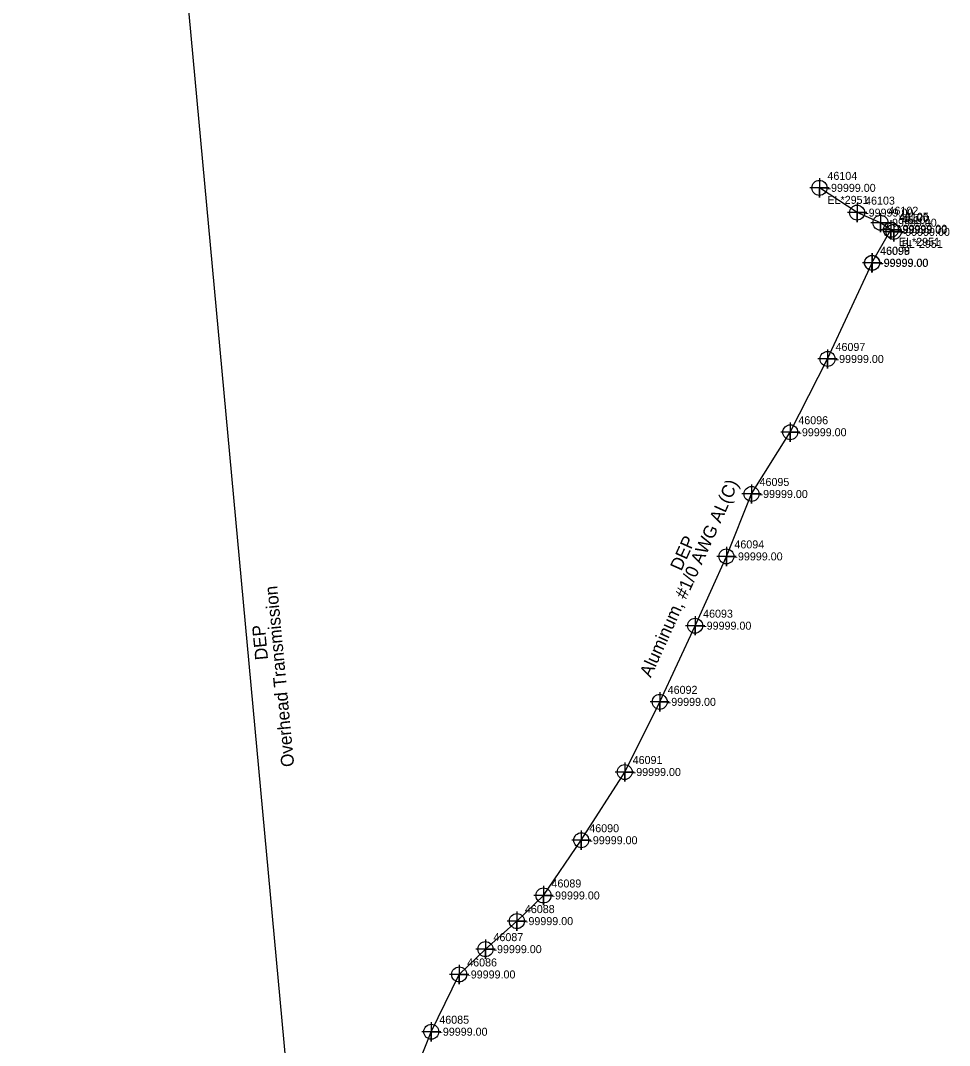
# Model space of a CAD drawing. Extents: x 2083698 to 2094313, y 743246 to 752873.
# Drawn here: x 2090968.3 to 2091258.4, y 750579.9 to 750900 of the extents above; entities that cross this region are included whole.
import ezdxf

# ---------------------------------------------------------------- set-up
doc = ezdxf.new("R2010")
doc.units = 0
for name, color, linetype in [('Exist Property Iron Pin Leader', 7, 'Continuous'), ('Exist Property Iron Pin Text', 7, 'Continuous'), ('Exist Property Monument Leader', 7, 'Continuous'), ('Exist Property Monument Text', 7, 'Continuous'), ('Exist Utilities Power Joint Use Telephone Cogo Elevation', 7, 'Continuous'), ('Exist Utilities Power Joint Use Telephone Cogo Number', 7, 'Continuous'), ('Exist Utilities Power UG Cable SUE LOS B', 7, 'Continuous'), ('Exist Utilities Power UG Cable SUE LOS B Text', 7, 'Continuous'), ('Exist Utilities Power UG Cable SUE LOS C', 7, 'Continuous'), ('Exist Utilities Power UG Cable SUE LOS C Text', 7, 'Continuous')]:
    doc.layers.add(name, color=color, linetype=linetype)

msp = doc.modelspace()

# ---------------------------------------------------------------- linework, layer by layer
at = {"layer": 'Exist Property Iron Pin Text'}
for points in [[(2091217.8, 750850.78), (2091217.8, 750844.78), (2091217.8, 750847.78), (2091220.8, 750847.78), (2091214.8, 750847.78)], [(2091229.56, 750843.04), (2091229.56, 750837.04), (2091229.56, 750840.04), (2091232.56, 750840.04), (2091226.56, 750840.04)], [(2091236.86, 750839.89), (2091236.86, 750833.89), (2091236.86, 750836.89), (2091239.86, 750836.89), (2091233.86, 750836.89)], [(2091240.12, 750837.67), (2091240.12, 750831.67), (2091240.12, 750834.67), (2091243.12, 750834.67), (2091237.12, 750834.67)], [(2091240.98, 750837.03), (2091240.98, 750831.03), (2091240.98, 750834.03), (2091243.98, 750834.03), (2091237.98, 750834.03)], [(2091234.21, 750827.33), (2091234.21, 750821.33), (2091234.21, 750824.33), (2091237.21, 750824.33), (2091231.21, 750824.33)], [(2091234.28, 750827.4), (2091234.28, 750821.4), (2091234.28, 750824.4), (2091237.28, 750824.4), (2091231.28, 750824.4)], [(2091220.33, 750797.34), (2091220.33, 750791.34), (2091220.33, 750794.34), (2091223.33, 750794.34), (2091217.33, 750794.34)], [(2091208.71, 750774.45), (2091208.71, 750768.45), (2091208.71, 750771.45), (2091211.71, 750771.45), (2091205.71, 750771.45)], [(2091196.6, 750755.17), (2091196.6, 750749.17), (2091196.6, 750752.17), (2091199.6, 750752.17), (2091193.6, 750752.17)], [(2091188.75, 750735.67), (2091188.75, 750729.67), (2091188.75, 750732.67), (2091191.75, 750732.67), (2091185.75, 750732.67)], [(2091178.98, 750714.03), (2091178.98, 750708.03), (2091178.98, 750711.03), (2091181.98, 750711.03), (2091175.98, 750711.03)], [(2091167.92, 750690.24), (2091167.92, 750684.24), (2091167.92, 750687.24), (2091170.92, 750687.24), (2091164.92, 750687.24)], [(2091156.99, 750668.33), (2091156.99, 750662.33), (2091156.99, 750665.33), (2091159.99, 750665.33), (2091153.99, 750665.33)], [(2091143.44, 750647.02), (2091143.44, 750641.02), (2091143.44, 750644.02), (2091146.44, 750644.02), (2091140.44, 750644.02)], [(2091131.64, 750629.77), (2091131.64, 750623.77), (2091131.64, 750626.77), (2091134.64, 750626.77), (2091128.64, 750626.77)], [(2091123.33, 750621.76), (2091123.33, 750615.76), (2091123.33, 750618.76), (2091126.33, 750618.76), (2091120.33, 750618.76)], [(2091113.52, 750613), (2091113.52, 750607), (2091113.52, 750610), (2091116.52, 750610), (2091110.52, 750610)], [(2091105.32, 750605.1), (2091105.32, 750599.1), (2091105.32, 750602.1), (2091108.32, 750602.1), (2091102.32, 750602.1)], [(2091096.61, 750587.21), (2091096.61, 750581.21), (2091096.61, 750584.21), (2091099.61, 750584.21), (2091093.61, 750584.21)]]:
    msp.add_lwpolyline(points, dxfattribs=at)
for centre in [(2091217.8, 750847.78), (2091229.56, 750840.04), (2091236.86, 750836.89), (2091240.12, 750834.67), (2091240.98, 750834.03), (2091234.21, 750824.33), (2091234.28, 750824.4), (2091220.33, 750794.34), (2091208.71, 750771.45), (2091196.6, 750752.17), (2091188.75, 750732.67), (2091178.98, 750711.03), (2091167.92, 750687.24), (2091156.99, 750665.33), (2091143.44, 750644.02), (2091131.64, 750626.77), (2091123.33, 750618.76), (2091113.52, 750610), (2091105.32, 750602.1), (2091096.61, 750584.21)]:
    msp.add_circle(centre, 2.34, dxfattribs=at)
at = {"layer": 'Exist Utilities Power UG Cable SUE LOS B'}
for points in [[(2091240.98, 750834.03), (2091236.86, 750836.89), (2091229.56, 750840.04), (2091217.8, 750847.78)], [(2091092.57, 750574.23), (2091096.61, 750584.21), (2091105.32, 750602.1), (2091113.52, 750610), (2091123.33, 750618.76), (2091131.64, 750626.77), (2091143.44, 750644.02), (2091156.99, 750665.33), (2091167.92, 750687.24), (2091178.98, 750711.03), (2091188.75, 750732.67), (2091196.6, 750752.17), (2091208.71, 750771.45), (2091220.33, 750794.34), (2091234.28, 750824.4), (2091234.21, 750824.33), (2091240.12, 750834.67)]]:
    msp.add_lwpolyline(points, dxfattribs=at)
at = {"layer": 'Exist Utilities Power UG Cable SUE LOS C'}
msp.add_lwpolyline([(2091181.56, 749137.25), (2091102.57, 750018.32), (2091019.27, 750921.35), (2090968.35, 751478.78)], dxfattribs=at)

# ---------------------------------------------------------------- texts
at = {"layer": 'Exist Property Iron Pin Leader'}
for s, p in [('46104', (2091220.3, 750850.28)), ('46103', (2091232.06, 750842.54)), ('46102', (2091239.36, 750839.39)), ('46100', (2091242.62, 750837.17)), ('46101', (2091243.48, 750836.53)), ('46099', (2091236.71, 750826.83)), ('46098', (2091236.78, 750826.9)), ('46097', (2091222.83, 750796.84)), ('46096', (2091211.21, 750773.95)), ('46095', (2091199.1, 750754.67)), ('46094', (2091191.25, 750735.17)), ('46093', (2091181.48, 750713.53)), ('46092', (2091170.42, 750689.74)), ('46091', (2091159.49, 750667.83)), ('46090', (2091145.94, 750646.52)), ('46089', (2091134.14, 750629.27)), ('46088', (2091125.83, 750621.26)), ('46087', (2091116.02, 750612.5)), ('46086', (2091107.82, 750604.6)), ('46085', (2091099.11, 750586.71))]:
    msp.add_text(s, height=2.5, dxfattribs=at).set_placement(p)
at = {"layer": 'Exist Property Monument Leader'}
for s, p in [('EL*2951', (2091220.3, 750842.78)), ('EL*2951', (2091242.62, 750829.67)), ('BL*2951', (2091243.48, 750829.03))]:
    msp.add_text(s, height=2.5, dxfattribs=at).set_placement(p)
at = {"layer": 'Exist Property Monument Text'}
for p in [(2091220.3, 750846.53), (2091232.06, 750838.79), (2091239.36, 750835.64), (2091242.62, 750833.42), (2091243.48, 750832.78), (2091236.71, 750823.08), (2091236.78, 750823.15), (2091222.83, 750793.09), (2091211.21, 750770.2), (2091199.1, 750750.92), (2091191.25, 750731.42), (2091181.48, 750709.78), (2091170.42, 750685.99), (2091159.49, 750664.08), (2091145.94, 750642.77), (2091134.14, 750625.52), (2091125.83, 750617.51), (2091116.02, 750608.75), (2091107.82, 750600.85), (2091099.11, 750582.96)]:
    msp.add_text('-99999.00', height=2.5, dxfattribs=at).set_placement(p)
at = {"layer": 'Exist Utilities Power Joint Use Telephone Cogo Elevation'}
msp.add_text('-99999.00', height=2.5, dxfattribs=at).set_placement((2091242.65, 750833.75))
at = {"layer": 'Exist Utilities Power Joint Use Telephone Cogo Number'}
msp.add_text('46105', height=2.5, dxfattribs=at).set_placement((2091242.65, 750837.5))
at = {"layer": 'Exist Utilities Power UG Cable SUE LOS B Text'}
for s, p in [('Aluminum, #1/0 AWG AL(C)', (2091165.14, 750694.59)), ('DEP', (2091174.66, 750727.89))]:
    msp.add_text(s, height=4, rotation=65.721, dxfattribs=at).set_placement(p)
at = {"layer": 'Exist Utilities Power UG Cable SUE LOS C Text'}
for s, p in [('Overhead Transmission', (2091053.83, 750667.1)), ('DEP', (2091045.64, 750700.49))]:
    msp.add_text(s, height=4, rotation=95.4056, dxfattribs=at).set_placement(p)

doc.saveas('drawing.dxf')
